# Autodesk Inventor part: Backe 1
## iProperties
Created: 2009-10
Part Number: Backe 1
Cost Center: 0 kg
Material: 3.3206 AlMgSi0,5
Description: Startmodell Bauteil
Document SubType Name: Modeling
Designer: BoseDa
Authority: 0 mm^3
Manufacturer: Standard
Standards Organization: Custom
Density: 2.66 g/cm^3
Company: Grenzebach BSH
Author: BoseDa
FileName: Norm
SaveDate: 2008-11-23
SaveTime: 16:30
TotalMass: 0 kg
TotalVolume: 0 mm^3
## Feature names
1. Extrusion2
